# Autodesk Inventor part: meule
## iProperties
Shininess: 64.0
Length Units: 11269
Angle Units: 11279
Time Units: 11290
Mass Units: 11283
Length Display Precision: 3
Angle Display Precision: 2
Compacted: True
Part Number: meule
Document SubType Name: Modeling
Created: 2005-01
Material: Par défaut
Designer: LEGERET Philippe
Density: 0.0
Volumn: 0.0
Area: 0.0
PropertySet Name: Model Information
Control State: 0
Master: False
Checked Out: False
Author: LEGERET Philippe
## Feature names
1. Extrusion1
2. Perçage1 [Hole]
3. Réseau circulaire1 [Circular Pattern]
